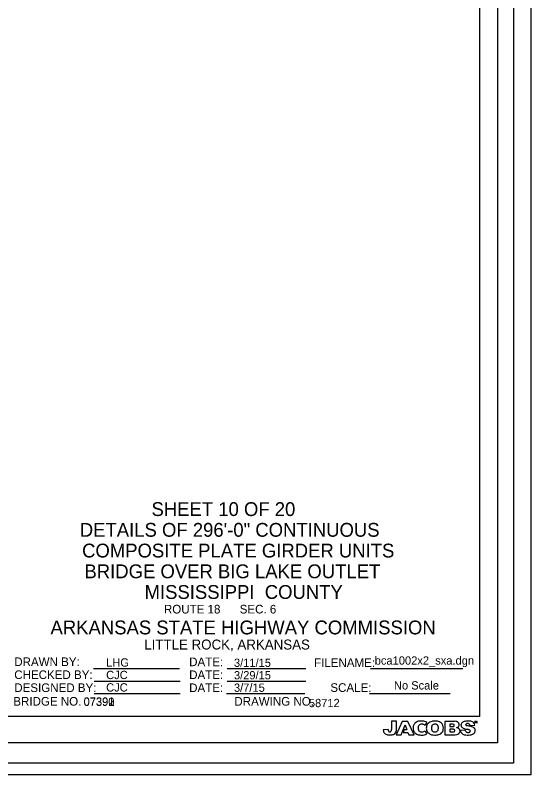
# Model space of a CAD drawing. Extents: x -725.7 to -683.7, y 85.6 to 107.6.
# Drawn here: x -698.65 to -691.19, y 85.62 to 96.61 of the extents above; entities that cross this region are included whole.
import ezdxf

# ---------------------------------------------------------------- set-up
doc = ezdxf.new("R2010")
doc.units = 0
for name, color, linetype in [('border', 7, 'Continuous'), ('Border 2660-Hwy18 - Level 62', 7, 'Continuous'), ('Border 2660-Hwy18 - Level 63', 7, 'Continuous'), ('Border 2660-Hwy18 - Text', 7, 'Continuous'), ('Border 2660-Hwy18 - Title Text', 7, 'Continuous'), ('Bridge No BLFR', 7, 'Continuous'), ('Bridge No BLO', 7, 'Continuous'), ('Bridge No Ditch 81', 7, 'Continuous'), ('Level 62 PDF', 7, 'Continuous'), ('Text', 7, 'Continuous'), ('Title Text', 7, 'Continuous')]:
    doc.layers.add(name, color=color, linetype=linetype)

msp = doc.modelspace()

# ---------------------------------------------------------------- linework, layer by layer
at = {"layer": 'border'}
for p, q in [((-691.93, 86.465), (-691.93, 107.01)), ((-697.518, 87.156), (-696.274, 87.156)), ((-695.584, 87.155), (-694.45, 87.155)), ((-693.514, 87.155), (-692.178, 87.155)), ((-697.51, 86.976), (-696.267, 86.976)), ((-695.584, 86.975), (-694.45, 86.975)), ((-697.51, 86.796), (-696.267, 86.796)), ((-695.595, 86.795), (-694.461, 86.795)), ((-693.527, 86.795), (-692.361, 86.795)), ((-691.93, 86.465), (-723.942, 86.465))]:
    msp.add_line(p, q, dxfattribs=at)
for points in [[(-693.136, 86.285), (-693.136, 86.395), (-693.21, 86.395), (-693.21, 86.275)], [(-693.013, 86.343), (-692.987, 86.272), (-693.026, 86.272), (-693.042, 86.23), (-692.971, 86.23), (-692.96, 86.197), (-692.882, 86.197), (-692.972, 86.393), (-693.052, 86.393), (-693.142, 86.197), (-693.067, 86.197), (-693.013, 86.343)], [(-692.296, 86.393), (-692.439, 86.393), (-692.439, 86.197)], [(-691.992, 86.391), (-692.007, 86.391), (-692.007, 86.389), (-692.001, 86.389), (-692.001, 86.372), (-691.998, 86.372), (-691.998, 86.389), (-691.992, 86.389), (-691.992, 86.391)], [(-691.987, 86.388), (-691.987, 86.388), (-691.981, 86.372), (-691.979, 86.372), (-691.973, 86.388), (-691.973, 86.388), (-691.973, 86.372), (-691.971, 86.372), (-691.971, 86.391), (-691.974, 86.391), (-691.98, 86.375), (-691.986, 86.391), (-691.99, 86.391), (-691.99, 86.372), (-691.987, 86.372), (-691.987, 86.388)], [(-693.257, 86.274), (-693.328, 86.27)], [(-692.332, 86.354), (-692.364, 86.354), (-692.364, 86.317)], [(-692.364, 86.317), (-692.33, 86.317)], [(-692.327, 86.279), (-692.364, 86.279), (-692.364, 86.239)], [(-692.143, 86.266), (-692.213, 86.262)], [(-692.074, 86.335), (-692.004, 86.338)], [(-692.439, 86.197), (-692.311, 86.197)], [(-692.364, 86.239), (-692.326, 86.239)]]:
    msp.add_lwpolyline(points, dxfattribs=at)
for centre, radius, start, end in [((-692.814, 86.308), 0.0809, 126.8513, 155.2444), ((-692.794, 86.282), 0.114, 94.7853, 126.8513), ((-692.773, 86.033), 0.363, 86.903, 94.7853), ((-692.76, 86.283), 0.113, 56.9246, 86.903), ((-692.473, 86.218), 0.276, 144.635, 154.8844), ((-692.626, 86.311), 0.0755, 123.8806, 148.6249), ((-692.589, 86.255), 0.142, 111.7104, 123.8806), ((-692.601, 86.286), 0.109, 96.5371, 111.7104), ((-692.57, 86.013), 0.384, 91.9058, 96.5371), ((-692.575, 86.231), 0.166, 73.4477, 92.4253), ((-692.56, 86.283), 0.112, 41.1934, 73.4477), ((-692.296, 86.29), 0.104, 72.1885, 90.1477), ((-692.283, 86.331), 0.0603, 61.4844, 72.1885), ((-692.281, 86.334), 0.0564, 34.7868, 61.4844), ((-692.261, 86.349), 0.0315, 16.9455, 34.7868), ((-692.156, 86.338), 0.0476, 124.08, 177.6485), ((-692.125, 86.292), 0.103, 108.2808, 124.08), ((-692.132, 86.313), 0.0811, 99.8173, 108.2808), ((-692.105, 86.154), 0.242, 93.402, 99.8173), ((-692.104, 86.143), 0.254, 80.6549, 93.402), ((-692.077, 86.305), 0.0897, 57.5906, 80.6549), ((-692.056, 86.339), 0.0494, 39.0736, 57.5906), ((-692.065, 86.332), 0.0612, 6.4385, 39.0736), ((-693.206, 86.28), 0.123, 184.5698, 198.1069), ((-693.197, 86.272), 0.0602, 178.2556, 191.4961), ((-693.229, 86.265), 0.0277, 191.4961, 218.7511), ((-693.239, 86.265), 0.0285, 325.4171, 349.1575), ((-693.289, 86.274), 0.0792, 349.1575, 360), ((-693.68, 86.345), 0.549, 350.0951, 351.3706), ((-693.259, 86.281), 0.124, 351.3706, 1.8291), ((-692.797, 86.301), 0.0987, 155.2444, 178.6811), ((-692.743, 86.299), 0.153, 178.6811, 194.3912), ((-692.835, 86.276), 0.0582, 194.3912, 214.1799), ((-692.719, 86.293), 0.104, 161.2834, 178.6702), ((-692.737, 86.293), 0.0855, 178.6702, 195.8531), ((-692.779, 86.281), 0.0421, 195.8531, 214.5369), ((-692.794, 86.318), 0.0243, 134.3139, 161.2834), ((-692.782, 86.28), 0.0388, 214.5369, 253.1918), ((-692.772, 86.296), 0.0556, 110.7655, 134.3139), ((-692.773, 86.298), 0.0529, 91.5073, 110.7655), ((-692.772, 86.236), 0.116, 82.6359, 91.5073), ((-692.763, 86.302), 0.0493, 65.5548, 82.6359), ((-692.792, 86.238), 0.119, 54.6002, 65.5548), ((-692.605, 86.298), 0.1, 148.6249, 181.2859), ((-692.553, 86.299), 0.152, 181.2859, 193.1956), ((-692.634, 86.28), 0.0683, 193.1956, 217.7499), ((-692.539, 86.295), 0.0917, 160.8611, 181.2981), ((-692.536, 86.295), 0.0951, 181.2981, 197.9492), ((-692.599, 86.316), 0.0287, 136.1177, 160.8611), ((-692.598, 86.275), 0.0299, 197.9492, 222.7741), ((-692.582, 86.3), 0.0518, 117.7176, 136.1177), ((-692.589, 86.312), 0.0382, 100.2108, 117.7176), ((-692.58, 86.261), 0.0895, 90.9675, 100.2108), ((-692.581, 86.289), 0.0622, 67.077, 90.4218), ((-692.571, 86.31), 0.0386, 24.6274, 67.077), ((-692.569, 86.278), 0.036, 299.5401, 342.4003), ((-692.587, 86.303), 0.056, 2.7442, 24.6274), ((-692.622, 86.294), 0.091, 342.4003, 0.0845), ((-692.78, 86.294), 0.249, 0.0845, 2.7442), ((-692.519, 86.318), 0.0579, 18.6966, 41.1934), ((-692.529, 86.279), 0.0698, 322.6714, 344.5708), ((-692.588, 86.295), 0.13, 344.5708, 18.6966), ((-692.333, 86.219), 0.135, 86.2098, 89.3498), ((-692.33, 86.38), 0.0633, 270.0363, 284.1438), ((-692.331, 86.032), 0.247, 86.6838, 88.8756), ((-692.328, 86.302), 0.0514, 74.8723, 86.2098), ((-692.32, 86.229), 0.0497, 75.9314, 86.6838), ((-692.319, 86.333), 0.0196, 40.2425, 74.8723), ((-692.319, 86.338), 0.0196, 284.1438, 307.8865), ((-692.316, 86.246), 0.0328, 59.6202, 75.9314), ((-692.316, 86.334), 0.0149, 307.8866, 341.4625), ((-692.313, 86.339), 0.0108, 21.9604, 40.2425), ((-692.321, 86.335), 0.0195, 341.4625, 21.9604), ((-692.307, 86.261), 0.015, 30.8341, 59.6202), ((-692.309, 86.26), 0.0177, 337.5037, 30.8341), ((-692.287, 86.375), 0.0753, 284.6785, 296.8411), ((-692.284, 86.211), 0.092, 61.0815, 79.9242), ((-692.274, 86.349), 0.0471, 296.8412, 329.8182), ((-692.258, 86.258), 0.039, 44.9773, 61.0815), ((-692.26, 86.341), 0.0307, 329.8182, 347.0949), ((-692.274, 86.345), 0.0455, 347.0949, 16.9455), ((-692.262, 86.253), 0.0452, 342.9845, 44.9773), ((-691.837, 86.315), 0.38, 187.9971, 189.0947), ((-692.162, 86.339), 0.0416, 177.6485, 218.8535), ((-692.151, 86.348), 0.0566, 218.8535, 233.6549), ((-692.137, 86.367), 0.0797, 233.6549, 244.7689), ((-692.104, 86.436), 0.156, 244.7689, 253.473), ((-692.057, 86.596), 0.323, 253.473, 259.8297), ((-692.091, 86.274), 0.0523, 188.5141, 201.638), ((-692.128, 86.345), 0.00815, 165.3108, 208.2887), ((-692.12, 86.343), 0.016, 146.4706, 165.3108), ((-692.12, 86.35), 0.0169, 211.7417, 226.6339), ((-692.126, 86.347), 0.00877, 130.7855, 146.4706), ((-692.115, 86.334), 0.0256, 97.3055, 130.7855), ((-692.122, 86.348), 0.0145, 226.6339, 245.1429), ((-692.105, 86.385), 0.0549, 245.1429, 260.9806), ((-692.109, 86.291), 0.0692, 81.3212, 97.3055), ((-692.189, 85.857), 0.479, 77.5139, 80.9806), ((-692.166, 85.986), 0.297, 76.0104, 79.8297), ((-692.104, 86.324), 0.0359, 57.474, 81.3212), ((-692.118, 86.179), 0.0974, 67.9593, 76.0104), ((-692.096, 86.337), 0.0202, 37.1977, 57.474), ((-692.513, 84.395), 1.977, 76.8035, 77.5139), ((-692.091, 86.245), 0.0265, 39.9313, 67.9593), ((-692.108, 86.328), 0.0351, 11.0051, 37.1977), ((-692.082, 86.253), 0.0145, 2.1813, 39.9313), ((-692.098, 86.161), 0.163, 65.6998, 76.8035), ((-692.063, 86.239), 0.0776, 51.3565, 65.6998), ((-692.048, 86.259), 0.0523, 36.5162, 51.3565), ((-692.045, 86.261), 0.0486, 345.1611, 36.5162), ((-693.273, 86.258), 0.0527, 198.1069, 225.9799), ((-693.254, 86.277), 0.0797, 225.9799, 261.0714), ((-693.228, 86.44), 0.244, 261.0714, 269.9405), ((-693.238, 86.258), 0.0164, 218.7511, 257.488), ((-693.234, 86.276), 0.0345, 257.488, 275.7834), ((-693.233, 86.267), 0.0257, 275.7834, 301.6926), ((-693.228, 86.363), 0.167, 269.9405, 279.1616), ((-693.226, 86.256), 0.0122, 301.6926, 325.4171), ((-693.217, 86.29), 0.0931, 279.1616, 305.8646), ((-693.196, 86.262), 0.0585, 305.8646, 338.7843), ((-693.191, 86.26), 0.0527, 338.7843, 350.0951), ((-692.778, 86.314), 0.127, 214.1799, 231.6615), ((-692.809, 86.275), 0.0765, 231.6616, 258.686), ((-692.766, 86.492), 0.298, 258.686, 268.8163), ((-692.771, 86.316), 0.0769, 253.1918, 291.1956), ((-692.769, 86.34), 0.146, 268.8163, 299.3878), ((-692.776, 86.331), 0.0928, 291.1956, 305.5144), ((-692.359, 86.438), 0.407, 206.7197, 213.678), ((-692.601, 86.306), 0.111, 217.7499, 244.1703), ((-692.612, 86.283), 0.0859, 244.1703, 259.4942), ((-692.573, 86.493), 0.299, 259.4942, 268.6426), ((-692.585, 86.287), 0.0474, 222.7741, 250.1955), ((-692.584, 86.29), 0.0507, 250.1955, 269.1264), ((-692.582, 86.431), 0.191, 269.1264, 272.0424), ((-692.576, 86.374), 0.18, 268.6426, 285.9017), ((-692.577, 86.291), 0.0512, 272.0424, 299.5401), ((-692.554, 86.298), 0.101, 285.9017, 322.6714), ((-692.326, 86.343), 0.104, 270.0001, 276.6749), ((-692.319, 86.283), 0.043, 276.6749, 293.0645), ((-692.321, 86.535), 0.338, 271.7224, 279.6279), ((-692.309, 86.26), 0.0178, 293.0645, 337.5037), ((-692.275, 86.262), 0.0609, 279.6279, 313.6357), ((-692.268, 86.255), 0.0511, 313.6357, 342.9845), ((-692.162, 86.263), 0.0503, 189.0947, 202.464), ((-692.127, 86.277), 0.0881, 202.464, 215.8926), ((-692.148, 86.262), 0.0621, 215.8926, 243.2968), ((-692.135, 86.288), 0.0904, 243.2968, 257.4598), ((-692.109, 86.407), 0.213, 257.4598, 268.8656), ((-692.11, 86.266), 0.0319, 201.638, 242.3635), ((-692.104, 86.278), 0.045, 242.3635, 264.6229), ((-692.102, 86.775), 0.581, 268.8656, 270.7612), ((-692.1, 86.313), 0.0806, 264.6229, 273.901), ((-692.098, 86.279), 0.0464, 273.901, 289.1925), ((-692.096, 86.372), 0.177, 270.7612, 282.5001), ((-692.092, 86.26), 0.0263, 289.1925, 322.566), ((-692.082, 86.253), 0.0141, 322.566, 2.1813), ((-692.081, 86.305), 0.109, 282.5001, 295.6144), ((-692.068, 86.276), 0.0772, 295.6144, 314.022), ((-692.056, 86.264), 0.0608, 314.022, 345.1611)]:
    msp.add_arc(centre, radius, start, end, dxfattribs=at)
at = {"layer": 'Border 2660-Hwy18 - Level 62'}
msp.add_lwpolyline([(-725.562, 107.596), (-691.443, 107.596), (-691.443, 85.786), (-725.562, 85.786)], close=True, dxfattribs=at)
at = {"layer": 'Border 2660-Hwy18 - Level 63'}
msp.add_lwpolyline([(-725.673, 107.453), (-691.673, 107.453), (-691.673, 86.083), (-725.673, 86.083)], close=True, dxfattribs=at)
at = {"layer": 'Level 62 PDF'}
msp.add_lwpolyline([(-725.312, 107.429), (-691.193, 107.429), (-691.193, 85.62), (-725.312, 85.62)], close=True, dxfattribs=at)

# ---------------------------------------------------------------- texts
at = {"layer": 'Border 2660-Hwy18 - Text'}
for s, p in [('DRAWN BY:', (-698.666, 87.192)), ('DATE:', (-696.136, 87.191)), ('FILENAME:', (-694.329, 87.179)), ('CHECKED BY:', (-698.666, 87.005)), ('DATE:', (-696.136, 87.004)), ('DESIGNED BY:', (-698.666, 86.817)), ('DATE:', (-696.136, 86.816)), ('SCALE:', (-694.093, 86.819)), ('BRIDGE NO.', (-698.68, 86.62)), ('DRAWING NO.', (-695.482, 86.62))]:
    msp.add_text(s, height=0.125, dxfattribs=at).set_placement(p)
at = {"layer": 'Border 2660-Hwy18 - Title Text'}
for s, height, p in [('MISSISSIPPI  COUNTY', 0.2, (-696.781, 88.164)), ('ROUTE 18      SEC. 6', 0.125, (-696.501, 87.953)), ('ARKANSAS STATE HIGHWAY COMMISSION', 0.2, (-698.142, 87.651)), ('LITTLE ROCK, ARKANSAS', 0.144, (-696.786, 87.432))]:
    msp.add_text(s, height=height, dxfattribs=at).set_placement(p)
at = {"layer": 'Bridge No BLFR'}
msp.add_text('07392', height=0.12, dxfattribs=at).set_placement((-697.663, 86.615))
at = {"layer": 'Bridge No BLO'}
msp.add_text('07391', height=0.12, dxfattribs=at).set_placement((-697.663, 86.62))
at = {"layer": 'Bridge No Ditch 81'}
msp.add_text('07390', height=0.12, dxfattribs=at).set_placement((-697.663, 86.615))
at = {"layer": 'Text'}
for s, p in [('LHG', (-697.337, 87.184)), ('3/11/15', (-695.488, 87.18)), ('bca1002x2_sxa.dgn', (-693.451, 87.213)), ('CJC', (-697.337, 87.004)), ('3/29/15', (-695.488, 87)), ('CJC', (-697.337, 86.824)), ('3/7/15', (-695.488, 86.82)), ('No Scale', (-693.173, 86.853)), ('58712', (-694.404, 86.598))]:
    msp.add_text(s, height=0.12, dxfattribs=at).set_placement(p)
at = {"layer": 'Title Text'}
for s, p in [('SHEET 10 OF 20', (-696.681, 89.363)), ('DETAILS OF 296\'-0" CONTINUOUS', (-697.718, 89.063)), ('COMPOSITE PLATE GIRDER UNITS', (-697.685, 88.763)), ('BRIDGE OVER BIG LAKE OUTLET', (-697.651, 88.463))]:
    msp.add_text(s, height=0.2, dxfattribs=at).set_placement(p)

doc.saveas('drawing.dxf')
